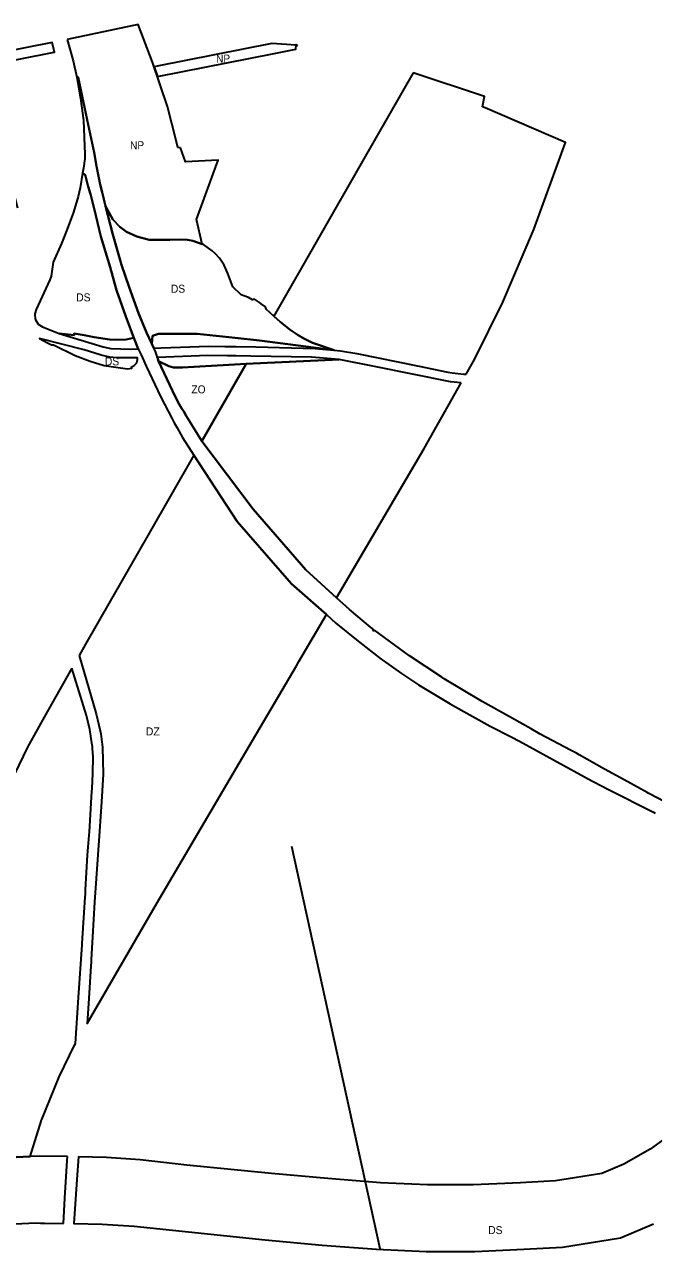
# Model space of a CAD drawing. Extents: x -650276 to -642489, y -1074311 to -1066658.
# Drawn here: x -647873 to -646929, y -1069094 to -1067254 of the extents above; entities that cross this region are included whole.
import ezdxf

# ---------------------------------------------------------------- set-up
doc = ezdxf.new("R2010")
doc.units = 0
doc.header["$LTSCALE"] = 4.8
doc.header["$PDMODE"] = 32
doc.header["$PDSIZE"] = 2.4
for name, color, linetype, lineweight in [('24', 7, 'Continuous', 35), ('25', 7, 'Continuous', 35), ('42', 7, 'Continuous', 35), ('48', 7, 'Continuous', 35), ('54', 7, 'Continuous', 35)]:
    doc.layers.add(name, color=color, linetype=linetype, lineweight=lineweight)
doc.layers.add('62', color=7, linetype='Continuous')

msp = doc.modelspace()

# ---------------------------------------------------------------- linework, layer by layer
at = {"layer": '24'}
for points in [[(-647606.818, -1067879.061), (-647617.25, -1067861.95), (-647625.37, -1067848.86), (-647630.3, -1067841.02), (-647633.69, -1067834.31), (-647637.21, -1067829.29), (-647642.29, -1067820.76), (-647650.8, -1067803.28), (-647672.05, -1067758.98), (-647673.47, -1067753.48), (-647673.47, -1067753.48), (-647674.67, -1067748.73), (-647676.47, -1067744.5), (-647678.66, -1067739.38), (-647681.91, -1067732.74), (-647690.09, -1067716.05), (-647702.04, -1067686.86), (-647715.92, -1067648.12), (-647727.37, -1067614.33), (-647740.49, -1067568.67), (-647751.41, -1067526.58), (-647756.55, -1067505.32), (-647759.16, -1067494.01), (-647764.89, -1067466.64), (-647768.5, -1067446.04), (-647778.78, -1067397.1), (-647792.52, -1067332.74), (-647794.54, -1067333.14), (-647788.77, -1067365.03), (-647784.55, -1067398.01), (-647782.39, -1067448.34), (-647782.5, -1067455.11), (-647784.36, -1067469.6), (-647785.64, -1067477.02), (-647781.85, -1067479.19), (-647777.55, -1067496.95), (-647773.96, -1067508.48), (-647768.5, -1067529.75), (-647758.25, -1067571.79), (-647744.61, -1067617.96), (-647734.63, -1067652.57), (-647721.05, -1067691.73), (-647708.71, -1067723.99), (-647702.21, -1067740.43), (-647699.89, -1067745.24), (-647697.85, -1067749.46), (-647695.71, -1067753.9), (-647690.19, -1067766.37), (-647668.13, -1067812.76), (-647651.94, -1067844.36), (-647648.33, -1067851.17), (-647643.83, -1067859.13), (-647635.77, -1067873.43), (-647618.773, -1067899.914)], [(-647708.71, -1067723.99), (-647721.05, -1067691.73), (-647734.63, -1067652.57), (-647744.61, -1067617.96), (-647758.25, -1067571.79), (-647768.5, -1067529.75), (-647773.96, -1067508.48), (-647777.55, -1067496.95), (-647781.85, -1067479.19), (-647785.64, -1067477.02), (-647789.39, -1067498.84), (-647792.54, -1067511.85), (-647799.39, -1067535.48)], [(-647799.39, -1067535.48), (-647808.71, -1067561.03), (-647817.59, -1067582.4)], [(-647654.743, -1067576.996), (-647685.968, -1067576.68), (-647704.458, -1067572.034), (-647719.661, -1067564.884), (-647729.802, -1067557.462), (-647740.124, -1067546.265), (-647751.41, -1067526.58)], [(-647751.41, -1067526.58), (-647740.49, -1067568.67), (-647727.37, -1067614.33), (-647715.92, -1067648.12), (-647702.04, -1067686.86)], [(-647606.559, -1067583.309), (-647620.586, -1067578.478), (-647628.441, -1067576.759), (-647640.087, -1067576.306), (-647654.743, -1067576.996)], [(-647817.59, -1067582.4), (-647829.97, -1067610.62), (-647832.8, -1067631.53), (-647835.06, -1067637.01), (-647855.24, -1067681.26), (-647857.51, -1067687.74), (-647856.9, -1067695.97)], [(-647547.663, -1067659.519), (-647560.187, -1067647.458), (-647567.744, -1067627.24), (-647573.605, -1067614.951), (-647580.539, -1067604.432), (-647586.864, -1067597.411), (-647591.227, -1067593.613), (-647604.415, -1067584.047), (-647606.559, -1067583.309)], [(-647499.095, -1067691.163), (-647503.97, -1067686.73), (-647510.6, -1067680.86), (-647511.24, -1067677.53), (-647517.74, -1067672.85), (-647520.13, -1067671.13), (-647527.76, -1067665.65), (-647530.82, -1067666.65), (-647536.83, -1067663.64), (-647547.663, -1067659.519)], [(-647702.04, -1067686.86), (-647690.09, -1067716.05), (-647681.91, -1067732.74)], [(-647856.9, -1067695.97), (-647852.3, -1067703.36), (-647845.74, -1067707.59), (-647821.02, -1067717.33)], [(-647462.45, -1067719.84), (-647474.13, -1067711.81), (-647489.3, -1067700.07), (-647499.095, -1067691.163)], [(-647783.54, -1067742.11), (-647850.45, -1067724.77), (-647838.18, -1067731.62), (-647832.56, -1067734.22), (-647829.49, -1067734.58), (-647796.87, -1067750.25), (-647774.54, -1067758.68), (-647753.53, -1067765.58), (-647718.54, -1067770.6), (-647712.01, -1067769.63), (-647712.26, -1067767.28)], [(-647821.02, -1067717.33), (-647798.5, -1067719.67), (-647798.17, -1067717.58), (-647783.13, -1067719.68), (-647768.53, -1067722.82), (-647745.41, -1067726.6), (-647732.71, -1067727.02), (-647720.45, -1067726.49), (-647708.71, -1067723.99)], [(-647681.91, -1067732.74), (-647680.804, -1067720.745), (-647672, -1067718), (-647643, -1067718), (-647614, -1067718)], [(-647614, -1067718), (-647557, -1067724), (-647520.145, -1067727.879), (-647408.2, -1067742.37), (-647440.81, -1067731.38), (-647453.87, -1067724.97), (-647462.45, -1067719.84)], [(-647712.26, -1067767.28), (-647711.773, -1067767.135), (-647711.286, -1067766.968), (-647710.799, -1067766.777), (-647710.315, -1067766.562), (-647709.834, -1067766.324), (-647709.359, -1067766.062), (-647708.892, -1067765.776), (-647708.433, -1067765.466), (-647707.985, -1067765.133), (-647707.55, -1067764.777), (-647707.128, -1067764.398), (-647706.723, -1067763.999), (-647706.335, -1067763.579), (-647705.966, -1067763.14), (-647705.617, -1067762.683), (-647705.29, -1067762.21), (-647704.985, -1067761.721), (-647704.704, -1067761.22), (-647704.447, -1067760.707), (-647704.216, -1067760.184), (-647704.01, -1067759.653), (-647703.83, -1067759.117), (-647703.675, -1067758.576), (-647703.547, -1067758.033), (-647703.445, -1067757.489), (-647703.368, -1067756.946), (-647703.315, -1067756.406), (-647703.287, -1067755.87), (-647703.282, -1067755.341), (-647703.3, -1067754.818), (-647703.34, -1067754.304), (-647703.4, -1067753.8), (-647711.09, -1067753.71), (-647728.98, -1067754.07), (-647734.69, -1067753.66), (-647744.74, -1067752.93), (-647757.74, -1067749.96), (-647759.13, -1067749.54), (-647783.54, -1067742.11)], [(-647405.026, -1068113.904), (-647451.024, -1068071.886), (-647530.038, -1067980.839), (-647606.818, -1067879.061)], [(-647618.773, -1067899.914), (-647553.628, -1067999.427), (-647472.338, -1068093.096), (-647419.713, -1068138.871)], [(-646864.48, -1068444.64), (-646936.47, -1068407.23), (-646938.95, -1068405.8), (-646967.64, -1068390), (-647002.71, -1068371.09), (-647040.77, -1068349.4), (-647044.93, -1068347.08), (-647053.75, -1068342.11), (-647099.2, -1068318.27), (-647112.813, -1068310.564), (-647142.41, -1068293.81), (-647186.26, -1068269.45), (-647243.39, -1068235.26), (-647246.8, -1068233.08), (-647295.47, -1068201.09), (-647347.74, -1068162.54), (-647349.59, -1068163.24), (-647350.6, -1068160.26), (-647353.81, -1068157.67), (-647385.13, -1068131.51), (-647405.026, -1068113.904)], [(-647419.713, -1068138.871), (-647405.71, -1068151.74), (-647372.38, -1068179.01), (-647337.74, -1068205.67), (-647334.62, -1068208.02), (-647307.39, -1068227.44), (-647281.64, -1068244.34), (-647234.11, -1068273.04), (-647230.83, -1068274.93), (-647174.56, -1068306.35), (-647142.788, -1068322.462), (-647130.29, -1068328.8), (-647079.16, -1068357.01), (-647032.91, -1068382.51), (-647029.23, -1068384.46), (-646997.06, -1068401.37), (-646929.56, -1068435.42), (-646927.06, -1068436.66)], [(-646894.206, -1068911.595), (-646934.465, -1068940.759), (-646973.61, -1068963.135), (-647006.63, -1068977.08), (-647076.422, -1068988.18), (-647128.674, -1068991.167), (-647199.672, -1068994.255), (-647268.348, -1068994.255), (-647338.816, -1068991.19), (-647417.895, -1068984.986), (-647502.412, -1068977.157), (-647629.424, -1068964.608), (-647699.561, -1068956.635), (-647749.978, -1068953.416), (-647792.01, -1068952.442), (-647794.21, -1068986.12), (-647796.13, -1069015.57), (-647798.631, -1069052.508), (-647756.441, -1069053.207), (-647708.401, -1069056.275), (-647511.94, -1069076.703), (-647426.417, -1069084.624), (-647344.902, -1069091.02), (-647270.522, -1069094.255), (-647197.498, -1069094.255), (-647123.648, -1069091.043), (-647065.688, -1069087.73), (-646978.92, -1069073.93), (-646929.186, -1069052.925)], [(-647864.531, -1068951.823), (-647895.901, -1068953.392), (-647958.168, -1068957.73), (-648038.596, -1068968.281), (-648038.759, -1068968.54)], [(-647808.28, -1068952.066), (-647850.043, -1068951.098), (-647864.531, -1068951.823)], [(-647814.401, -1069052.246), (-647812.34, -1069014.54), (-647808.67, -1068958.06), (-647808.28, -1068952.066)], [(-648040.705, -1069069.547), (-648039.666, -1069069.279), (-647948.18, -1069057.276), (-647886.615, -1069053.052), (-647856.541, -1069051.548), (-647848.615, -1069051.679), (-647842.888, -1069051.774), (-647814.401, -1069052.246)]]:
    msp.add_lwpolyline(points, dxfattribs=at)
for points in [[(-647754.88, -1067737.59), (-647743.12, -1067739.93), (-647728.29, -1067740.64), (-647713.15, -1067741), (-647702.21, -1067740.43), (-647708.71, -1067723.99), (-647720.45, -1067726.49), (-647732.71, -1067727.02), (-647745.41, -1067726.6), (-647768.53, -1067722.82), (-647783.13, -1067719.68), (-647798.17, -1067717.58), (-647798.5, -1067719.67), (-647821.02, -1067717.33)], [(-647596.91, -1067736.61), (-647572.33, -1067737.03), (-647555.58, -1067736.71), (-647525.685, -1067737.542), (-647436.72, -1067740.02), (-647408.2, -1067742.37), (-647520.145, -1067727.879), (-647557, -1067724), (-647614, -1067718), (-647643, -1067718), (-647672, -1067718), (-647680.804, -1067720.745), (-647681.91, -1067732.74), (-647678.66, -1067739.38), (-647678.66, -1067739.38), (-647667.76, -1067739.01), (-647638.75, -1067738.03)], [(-647540.208, -1067762.876), (-647400.63, -1067756.19), (-647442.6, -1067753.13), (-647533.597, -1067751.344), (-647555.67, -1067750.91), (-647568.36, -1067750.7), (-647597.83, -1067750.21), (-647673.47, -1067753.48), (-647672.05, -1067758.98), (-647672.05, -1067758.98), (-647656.469, -1067766.309), (-647649.22, -1067768.38), (-647635.758, -1067768.38)], [(-647540.208, -1067762.876), (-647400.63, -1067756.19), (-647442.6, -1067753.13), (-647533.597, -1067751.344), (-647555.67, -1067750.91), (-647568.36, -1067750.7), (-647597.83, -1067750.21), (-647673.47, -1067753.48), (-647672.05, -1067758.98), (-647672.05, -1067758.98), (-647656.469, -1067766.309), (-647649.22, -1067768.38), (-647635.758, -1067768.38)]]:
    msp.add_lwpolyline(points, close=True, dxfattribs=at)
at = {"layer": '25'}
for points in [[(-647289.924, -1067326.309), (-647364.024, -1067455.561), (-647499.095, -1067691.163), (-647489.3, -1067700.07)], [(-647185.93, -1067377.38), (-647183.09, -1067362.16), (-647289.924, -1067326.309)], [(-647210.537, -1067778.594), (-647198.088, -1067756.5), (-647155.592, -1067670.17), (-647108.971, -1067561.55), (-647061.252, -1067430.908), (-647181.878, -1067379.12), (-647185.93, -1067377.38)], [(-647489.3, -1067700.07), (-647474.13, -1067711.81), (-647462.45, -1067719.84), (-647453.87, -1067724.97), (-647440.81, -1067731.38), (-647408.2, -1067742.37), (-647398.74, -1067743.15)], [(-647398.74, -1067743.15), (-647374.55, -1067747.34), (-647280.78, -1067766.44), (-647237.91, -1067775.18), (-647231.17, -1067776.55), (-647213.92, -1067778.26), (-647210.537, -1067778.594)], [(-647400.63, -1067756.19), (-647540.208, -1067762.876), (-647593.267, -1067855.425), (-647606.818, -1067879.061)], [(-647217.611, -1067791.149), (-647233.83, -1067789.69), (-647345.11, -1067767.28), (-647400.63, -1067756.19)], [(-647405.026, -1068113.904), (-647273.297, -1067889.981), (-647217.611, -1067791.149)], [(-647606.818, -1067879.061), (-647530.038, -1067980.839), (-647451.024, -1068071.886), (-647405.026, -1068113.904)], [(-647464.94, -1068215.752), (-647461.188, -1068209.373), (-647419.713, -1068138.871), (-647472.338, -1068093.096), (-647553.628, -1067999.427), (-647618.773, -1067899.914), (-647685.819, -1068016.861)], [(-647685.819, -1068016.861), (-647781.346, -1068183.485), (-647791.055, -1068200.507)], [(-647791.055, -1068200.507), (-647765.22, -1068287.94), (-647759.412, -1068313.436)], [(-647801.797, -1068219.34), (-647843.6, -1068292.629), (-647868.214, -1068337.803), (-647914.339, -1068432.512), (-647946.187, -1068510.254), (-647971.074, -1068581.98), (-647997.27, -1068674.747), (-648011.775, -1068739.718), (-648023.914, -1068809.332), (-648030.73, -1068861.213), (-648038.596, -1068968.281)], [(-647771.413, -1068334.626), (-647774.94, -1068311.47), (-647779.55, -1068292.23), (-647780.07, -1068290.53), (-647801.797, -1068219.34)], [(-647768.02, -1068570.36), (-647770.94, -1068622.47), (-647772.85, -1068656.41), (-647773.08, -1068660.57), (-647773.4, -1068665.71), (-647776.5, -1068714.8), (-647778.95, -1068752.433), (-647675.054, -1068572.919), (-647535.844, -1068336.279), (-647464.94, -1068215.752)], [(-647759.412, -1068313.436), (-647758.45, -1068317.66), (-647756.09, -1068337.61), (-647754.99, -1068378.21), (-647757.41, -1068419.98), (-647760.22, -1068463.96), (-647768.02, -1068570.36)], [(-647796.173, -1068782.191), (-647791.77, -1068713.23), (-647786.47, -1068634.37), (-647786.32, -1068632.19), (-647781.85, -1068562.97), (-647781.55, -1068558.38), (-647781.13, -1068551.88), (-647778.24, -1068499.95), (-647775.82, -1068469.74), (-647775.52, -1068464.97), (-647771.74, -1068404.5), (-647771.47, -1068400.07), (-647770.12, -1068377.5), (-647769.92, -1068352.1), (-647770.81, -1068340.29), (-647771.05, -1068337.01), (-647771.413, -1068334.626)], [(-647846.989, -1068896.545), (-647820.883, -1068832.117), (-647797.632, -1068784.713), (-647796.173, -1068782.191)], [(-647958.168, -1068957.73), (-647895.901, -1068953.392), (-647864.531, -1068951.823), (-647847.197, -1068897.199), (-647847.034, -1068896.687), (-647846.989, -1068896.545)]]:
    msp.add_lwpolyline(points, dxfattribs=at)
at = {"layer": '42'}
msp.add_lwpolyline([(-647606.818, -1067879.061), (-647540.208, -1067762.876), (-647635.758, -1067768.38), (-647649.22, -1067768.38), (-647656.469, -1067766.309), (-647672.05, -1067758.98), (-647650.8, -1067803.28), (-647642.29, -1067820.76), (-647637.21, -1067829.29), (-647633.69, -1067834.31), (-647630.3, -1067841.02), (-647625.37, -1067848.86), (-647617.25, -1067861.95)], close=True, dxfattribs=at)
at = {"layer": '48'}
for points in [[(-647638.68, -1067439.06), (-647642.686, -1067438.46), (-647645.78, -1067425.81), (-647658.13, -1067376.99), (-647680.64, -1067310.37), (-647702.42, -1067253.98), (-647809.02, -1067276.271)], [(-647882.66, -1067529.231), (-647926.759, -1067358.379), (-647937.355, -1067316.774), (-647828.376, -1067295.406), (-647828.104, -1067295.352), (-647831.28, -1067280.69), (-647948.488, -1067303.671)], [(-647809.02, -1067276.271), (-647799.76, -1067308.3), (-647794.54, -1067333.14)], [(-647465.203, -1067285.115), (-647501.968, -1067282.642), (-647673.685, -1067316.666), (-647678.21, -1067317.562), (-647673.367, -1067331.895), (-647670.77, -1067331.38), (-647501.099, -1067297.762)], [(-647501.099, -1067297.762), (-647465.699, -1067290.747), (-647465.203, -1067285.115)], [(-647794.54, -1067333.14), (-647792.52, -1067332.74), (-647778.78, -1067397.1), (-647768.5, -1067446.04), (-647764.89, -1067466.64), (-647759.16, -1067494.01)], [(-647751.41, -1067526.58), (-647740.124, -1067546.265), (-647729.802, -1067557.462), (-647719.661, -1067564.884), (-647704.458, -1067572.034), (-647685.968, -1067576.68), (-647654.743, -1067576.996), (-647640.087, -1067576.306), (-647628.441, -1067576.759), (-647620.586, -1067578.478), (-647606.559, -1067583.309), (-647614.75, -1067546.53), (-647582.2, -1067457.65), (-647631.59, -1067459.72), (-647638.68, -1067439.06)], [(-647759.16, -1067494.01), (-647756.55, -1067505.32), (-647751.41, -1067526.58)]]:
    msp.add_lwpolyline(points, dxfattribs=at)
msp.add_point((-647465.203, -1067285.115), dxfattribs=at)
at = {"layer": '54'}
msp.add_line((-647472.11, -1068486.2), (-647340, -1069090), dxfattribs=at)

# ---------------------------------------------------------------- texts
at = {"layer": '62', "width": 0.95}
for s, p in [('NP', (-647585.583, -1067311.041)), ('NP', (-647714.583, -1067441.041)), ('DS', (-647653.118, -1067656.225)), ('DS', (-647795.118, -1067669.225)), ('DS', (-647752.118, -1067765.225)), ('ZO', (-647622.423, -1067807.188)), ('DS', (-647177.118, -1069068.225))]:
    msp.add_text(s, height=12, dxfattribs=at).set_placement(p)
at = {"layer": '62'}
msp.add_text('DZ', height=12, dxfattribs=at).set_placement((-647691.118, -1068320.225))

doc.saveas('drawing.dxf')
